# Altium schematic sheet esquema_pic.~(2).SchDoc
size A4
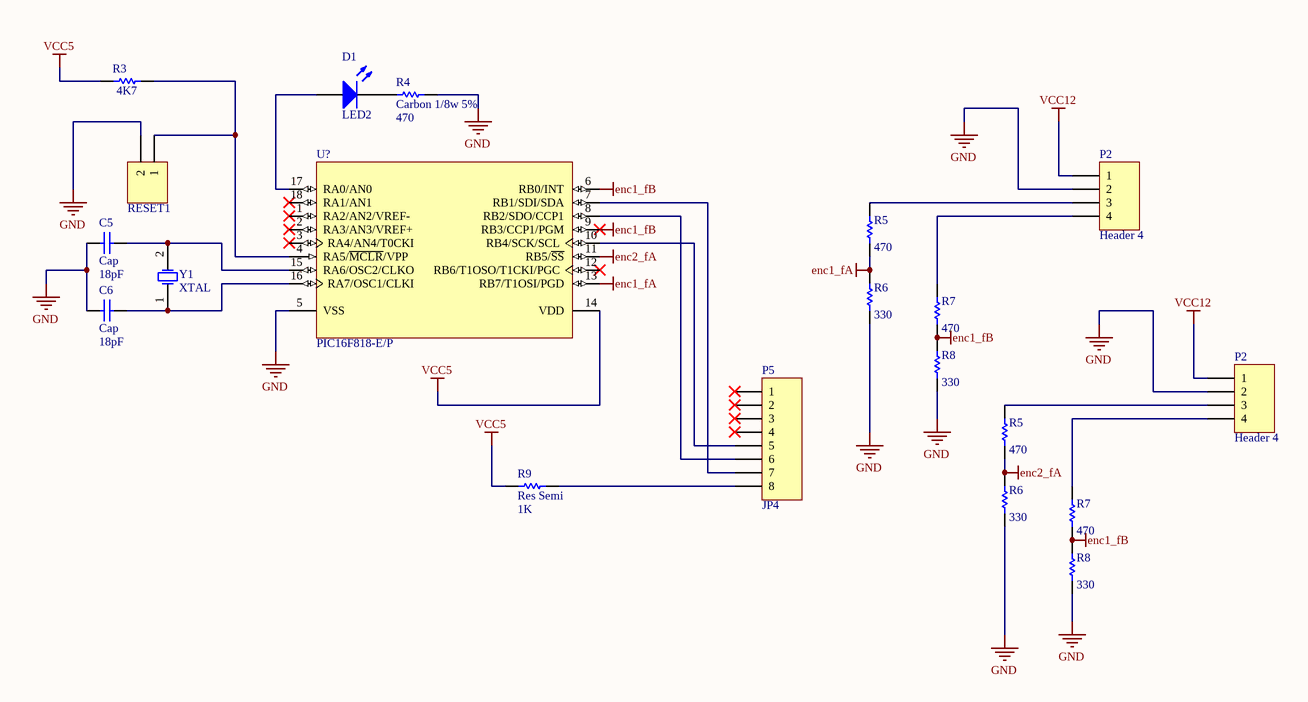
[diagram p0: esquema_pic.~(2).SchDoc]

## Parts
(Parts that share a designator on the sheet are numbered #1, #2 ... from top to bottom, then left to right.)
C5  Cap  value 18pF  [RAD-0.3]
C6  Cap  value 18pF  [RAD-0.3]
D1  LED2  [3.2X1.6X1.1]
P2#1  Header 4  [HDR1X4]
P2#2  Header 4  [HDR1X4]
P5  JP4  [HDR1X8H]
R3  value 4K7  [1005[0402]]  (hidden comment: Carbon 1/8w 5%)
R4  Carbon 1/8w 5%  value 470  [1005[0402]]
R5#1  value 470  [1005[0402]]  (hidden comment: metal film 2%)
R5#2  value 470  [1005[0402]]  (hidden comment: metal film 2%)
R6#1  value 330  [1005[0402]]  (hidden comment: metal film 2%)
R6#2  value 330  [1005[0402]]  (hidden comment: metal film 2%)
R7#1  value 470  [1005[0402]]  (hidden comment: metal film 2%)
R7#2  value 470  [1005[0402]]  (hidden comment: metal film 2%)
R8#1  value 330  [1005[0402]]  (hidden comment: metal film 2%)
R8#2  value 330  [1005[0402]]  (hidden comment: metal film 2%)
R9  Res Semi  value 1K  [1005[0402]]
RESET1  Header 2  [HDR1X2]  (value not drawn)
U?  PIC16F818-E/P  [PDIP300-18]
Y1  XTAL  [R38]

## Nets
enc1_fA: R5#1.1 R6#1.2 U?.13(RB7/T1OSI/PGD)
enc1_fB: R7#1.1 R7#2.1 R8#1.2 R8#2.2 U?.6(RB0/INT) U?.9(RB3/CCP1/PGM)
enc2_fA: R5#2.1 R6#2.2 U?.11(RB5/~{SS})
GND: C5.1 C6.1 P2#1.2 P2#2.2 R4.2 R6#1.1 R6#2.1 R8#1.1 R8#2.1 RESET1.2 U?.5(VSS)
VCC5: R3.1 R9.1 U?.14(VDD)
VCC12: P2#1.1 P2#2.1
NetC5_2: C5.2 U?.15(RA6/OSC2/CLKO) Y1.2(OSC2)
NetC6_2: C6.2 U?.16(RA7/OSC1/CLKI) Y1.1(OSC1)
NetD1_1: D1.1(A) U?.17(RA0/AN0)
NetD1_2: D1.2(K) R4.1
NetP2#1_3: P2#1.3 R5#1.2
NetP2#1_4: P2#1.4 R7#1.2
NetP2#2_3: P2#2.3 R5#2.2
NetP2#2_4: P2#2.4 R7#2.2
NetP5_5: P5.5 U?.10(RB4/SCK/SCL)
NetP5_6: P5.6 U?.8(RB2/SDO/CCP1)
NetP5_7: P5.7 U?.7(RB1/SDI/SDA)
NetP5_8: P5.8 R9.2
NetR3_2: R3.2 RESET1.1 U?.4(RA5/~{MCLR}/VPP)

Not connected (* = marked no-connect by the designer): P5 1* 2* 3* 4*; U? 1(RA2/AN2/VREF-)* 2(RA3/AN3/VREF+)* 3(RA4/AN4/T0CKI)* 12(RB6/T1OSO/T1CKI/PGC)* 18(RA1/AN1)*

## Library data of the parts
C5 C6 = Cap: Capacitor
D1 = LED2: Typical RED, GREEN, YELLOW, AMBER GaAs LED
P2#1 P2#2 = Header 4: Header, 4-Pin
P5 = Header 8H: Header, 8-Pin, Right Angle
R3 R4 R5#1 R5#2 R6#1 R6#2 R7#1 R7#2 R8#1 R8#2 R9 = Res Semi: Semiconductor Resistor
RESET1 = Header 2: Header, 2-Pin
U? = PIC16F818-E/P: Enhanced FLASH Microcontroller with nanoWatt Technology, 1K (x14-Bit words) FLASH, 128 Bytes RAM, 18-Pin PDIP, Standard VDD Range, Extended Temperature
Y1 = XTAL: Crystal Oscillator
